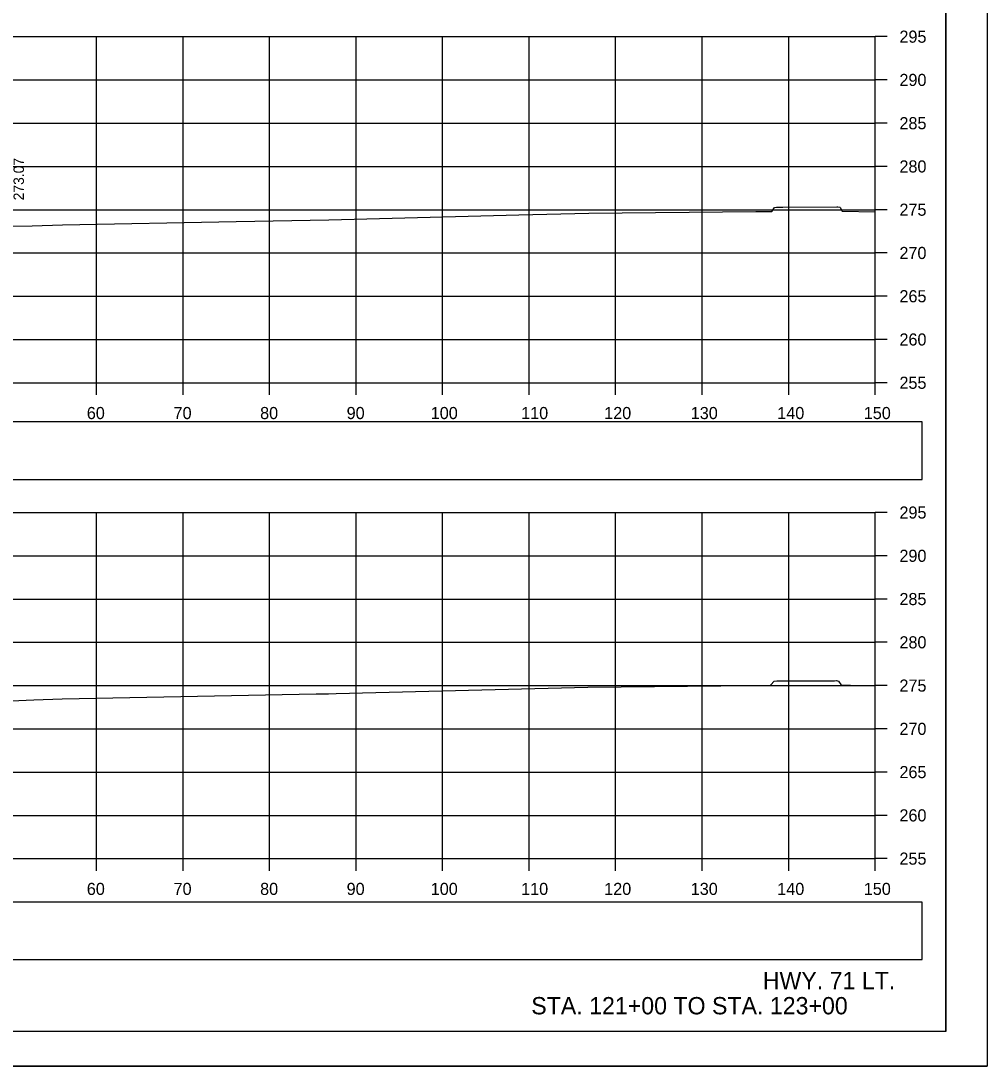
# Model space of a CAD drawing. Extents: x 285 to 4233, y -659 to 3710.
# Drawn here: x 590.5 to 702.2, y 1042.9 to 1163.7 of the extents above; entities that cross this region are included whole.
import ezdxf

# ---------------------------------------------------------------- set-up
doc = ezdxf.new("R2010")
doc.units = 0
for name, color, linetype in [('R_Axis', 7, 'Continuous'), ('R_Axis Annot', 7, 'Continuous'), ('R_Border', 7, 'Continuous'), ('R_Draft', 7, 'Continuous'), ('R_Exist Surface', 7, 'Continuous'), ('R_Grid', 7, 'Continuous'), ('R_No Plot', 7, 'Continuous'), ('R_Xsect Elev', 7, 'Continuous')]:
    doc.layers.add(name, color=color, linetype=linetype)

msp = doc.modelspace()

# ---------------------------------------------------------------- linework, layer by layer
at = {"layer": 'R_Axis'}
for p, q in [((689.28, 1121.84), (689.28, 1161.84)), ((690.68, 1161.84), (689.28, 1161.84)), ((690.68, 1156.84), (689.28, 1156.84)), ((690.68, 1151.84), (689.28, 1151.84)), ((690.68, 1146.84), (689.28, 1146.84)), ((690.68, 1141.84), (689.28, 1141.84)), ((690.68, 1136.84), (689.28, 1136.84)), ((690.68, 1131.84), (689.28, 1131.84)), ((690.68, 1126.84), (689.28, 1126.84)), ((389.28, 1121.84), (689.28, 1121.84)), ((599.28, 1120.44), (599.28, 1121.84)), ((609.28, 1120.44), (609.28, 1121.84)), ((619.28, 1120.44), (619.28, 1121.84)), ((629.28, 1120.44), (629.28, 1121.84)), ((639.28, 1120.44), (639.28, 1121.84)), ((649.28, 1120.44), (649.28, 1121.84)), ((659.28, 1120.44), (659.28, 1121.84)), ((669.28, 1120.44), (669.28, 1121.84)), ((679.28, 1120.44), (679.28, 1121.84)), ((689.28, 1120.44), (689.28, 1121.84)), ((690.68, 1121.84), (689.28, 1121.84)), ((689.28, 1066.84), (689.28, 1106.84)), ((690.68, 1106.84), (689.28, 1106.84)), ((690.68, 1101.84), (689.28, 1101.84)), ((690.68, 1096.84), (689.28, 1096.84)), ((690.68, 1091.84), (689.28, 1091.84)), ((690.68, 1086.84), (689.28, 1086.84)), ((690.68, 1081.84), (689.28, 1081.84)), ((690.68, 1076.84), (689.28, 1076.84)), ((690.68, 1071.84), (689.28, 1071.84)), ((389.28, 1066.84), (689.28, 1066.84)), ((599.28, 1065.44), (599.28, 1066.84)), ((609.28, 1065.44), (609.28, 1066.84)), ((619.28, 1065.44), (619.28, 1066.84)), ((629.28, 1065.44), (629.28, 1066.84)), ((639.28, 1065.44), (639.28, 1066.84)), ((649.28, 1065.44), (649.28, 1066.84)), ((659.28, 1065.44), (659.28, 1066.84)), ((669.28, 1065.44), (669.28, 1066.84)), ((679.28, 1065.44), (679.28, 1066.84)), ((689.28, 1065.44), (689.28, 1066.84)), ((690.68, 1066.84), (689.28, 1066.84))]:
    msp.add_line(p, q, dxfattribs=at)
at = {"layer": 'R_Axis Annot'}
for points in [[(554.36, 1110.67), (694.72, 1110.67), (694.72, 1117.32), (554.36, 1117.32)], [(554.36, 1055.17), (694.72, 1055.17), (694.72, 1061.82), (554.36, 1061.82)]]:
    msp.add_lwpolyline(points, close=True, dxfattribs=at)
at = {"layer": 'R_Border'}
for q in [(697.46, 1252.3), (381.28, 1046.84)]:
    msp.add_line((697.46, 1046.84), q, dxfattribs=at)
at = {"layer": 'R_Exist Surface'}
for points in [[(589.3, 1139.92), (591.83, 1139.99), (595.37, 1140.1), (615.41, 1140.47), (626.15, 1140.67), (648.1, 1141.25), (656.19, 1141.45), (675.49, 1141.62), (677.33, 1141.64), (677.36, 1141.68), (677.63, 1142.09), (677.87, 1142.12), (677.89, 1142.12), (678.02, 1142.12), (678.03, 1142.12), (678.59, 1142.13), (684.84, 1142.18), (684.85, 1142.18), (684.96, 1142.18), (685.19, 1142.14), (685.21, 1142.13), (685.23, 1142.1), (685.45, 1141.69), (689.28, 1141.61)], [(589.42, 1085.09), (592.04, 1085.18), (595.33, 1085.29), (624.66, 1085.87), (626.08, 1085.9), (626.99, 1085.92), (656.08, 1086.66), (675.28, 1086.85), (677.2, 1086.88), (677.23, 1086.91), (677.59, 1087.34), (677.61, 1087.34), (677.92, 1087.37), (677.96, 1087.37), (677.96, 1087.37), (684.11, 1087.39), (684.56, 1087.39), (684.79, 1087.41), (684.8, 1087.41), (684.82, 1087.41), (685.03, 1087.36), (685.31, 1086.95), (685.33, 1086.92), (686.44, 1086.9), (689.28, 1086.84)]]:
    msp.add_lwpolyline(points, dxfattribs=at)
at = {"layer": 'R_Grid'}
for p, q in [((389.28, 1161.84), (689.28, 1161.84)), ((599.28, 1121.84), (599.28, 1161.84)), ((609.28, 1121.84), (609.28, 1161.84)), ((619.28, 1121.84), (619.28, 1161.84)), ((629.28, 1121.84), (629.28, 1161.84)), ((639.28, 1121.84), (639.28, 1161.84)), ((649.28, 1121.84), (649.28, 1161.84)), ((659.28, 1121.84), (659.28, 1161.84)), ((669.28, 1121.84), (669.28, 1161.84)), ((679.28, 1121.84), (679.28, 1161.84)), ((689.28, 1121.84), (689.28, 1161.84)), ((389.28, 1156.84), (689.28, 1156.84)), ((389.28, 1151.84), (689.28, 1151.84)), ((389.28, 1146.84), (689.28, 1146.84)), ((389.28, 1141.84), (689.28, 1141.84)), ((389.28, 1136.84), (689.28, 1136.84)), ((389.28, 1131.84), (689.28, 1131.84)), ((389.28, 1126.84), (689.28, 1126.84)), ((389.28, 1121.84), (689.28, 1121.84)), ((389.28, 1106.84), (689.28, 1106.84)), ((599.28, 1066.84), (599.28, 1106.84)), ((609.28, 1066.84), (609.28, 1106.84)), ((619.28, 1066.84), (619.28, 1106.84)), ((629.28, 1066.84), (629.28, 1106.84)), ((639.28, 1066.84), (639.28, 1106.84)), ((649.28, 1066.84), (649.28, 1106.84)), ((659.28, 1066.84), (659.28, 1106.84)), ((669.28, 1066.84), (669.28, 1106.84)), ((679.28, 1066.84), (679.28, 1106.84)), ((689.28, 1066.84), (689.28, 1106.84)), ((389.28, 1101.84), (689.28, 1101.84)), ((389.28, 1096.84), (689.28, 1096.84)), ((389.28, 1091.84), (689.28, 1091.84)), ((389.28, 1086.84), (689.28, 1086.84)), ((389.28, 1081.84), (689.28, 1081.84)), ((389.28, 1076.84), (689.28, 1076.84)), ((389.28, 1071.84), (689.28, 1071.84)), ((389.28, 1066.84), (689.28, 1066.84))]:
    msp.add_line(p, q, dxfattribs=at)
at = {"layer": 'R_No Plot'}
msp.add_line((368.88, 1042.86), (702.21, 1042.86), dxfattribs=at)
for points in [[(368.87, 1256.2), (702.21, 1256.2), (702.21, 1042.86), (368.87, 1042.86)], [(615.2, 1252.3), (634.82, 1252.3), (634.82, 1242.42), (650.93, 1242.42), (674.13, 1242.42), (674.25, 1214.27), (697.46, 1214.27), (697.46, 1046.84), (381.28, 1046.84), (381.28, 1252.3)]]:
    msp.add_lwpolyline(points, close=True, dxfattribs=at)

# ---------------------------------------------------------------- texts
at = {"layer": 'R_Axis Annot'}
for s, p in [('295', (692.08, 1161.14)), ('290', (692.08, 1156.14)), ('285', (692.08, 1151.14)), ('280', (692.08, 1146.14)), ('275', (692.08, 1141.14)), ('270', (692.08, 1136.14)), ('265', (692.08, 1131.14)), ('260', (692.08, 1126.14)), ('255', (692.08, 1121.14)), ('60', (598.16, 1117.64)), ('70', (608.19, 1117.64)), ('80', (618.19, 1117.64)), ('90', (628.19, 1117.64)), ('100', (637.91, 1117.64)), ('110', (648.36, 1117.64)), ('120', (657.96, 1117.64)), ('130', (667.96, 1117.64)), ('140', (677.96, 1117.64)), ('150', (687.96, 1117.64)), ('295', (692.08, 1106.14)), ('290', (692.08, 1101.14)), ('285', (692.08, 1096.14)), ('280', (692.08, 1091.14)), ('275', (692.08, 1086.14)), ('270', (692.08, 1081.14)), ('265', (692.08, 1076.14)), ('260', (692.08, 1071.14)), ('255', (692.08, 1066.14)), ('60', (598.16, 1062.64)), ('70', (608.19, 1062.64)), ('80', (618.19, 1062.64)), ('90', (628.19, 1062.64)), ('100', (637.91, 1062.64)), ('110', (648.36, 1062.64)), ('120', (657.96, 1062.64)), ('130', (667.96, 1062.64)), ('140', (677.96, 1062.64)), ('150', (687.96, 1062.64))]:
    msp.add_text(s, height=1.4, dxfattribs=at).set_placement(p)
at = {"layer": 'R_Draft'}
for s, p in [('HWY. 71 LT.', (676.29, 1051.75)), ('STA. 121+00 TO STA. 123+00', (649.53, 1048.84))]:
    msp.add_text(s, height=2, dxfattribs=at).set_placement(p)
at = {"layer": 'R_Xsect Elev'}
msp.add_text('273.07', height=1.2, rotation=90, dxfattribs=at).set_placement((590.89, 1142.92))

doc.saveas('drawing.dxf')
